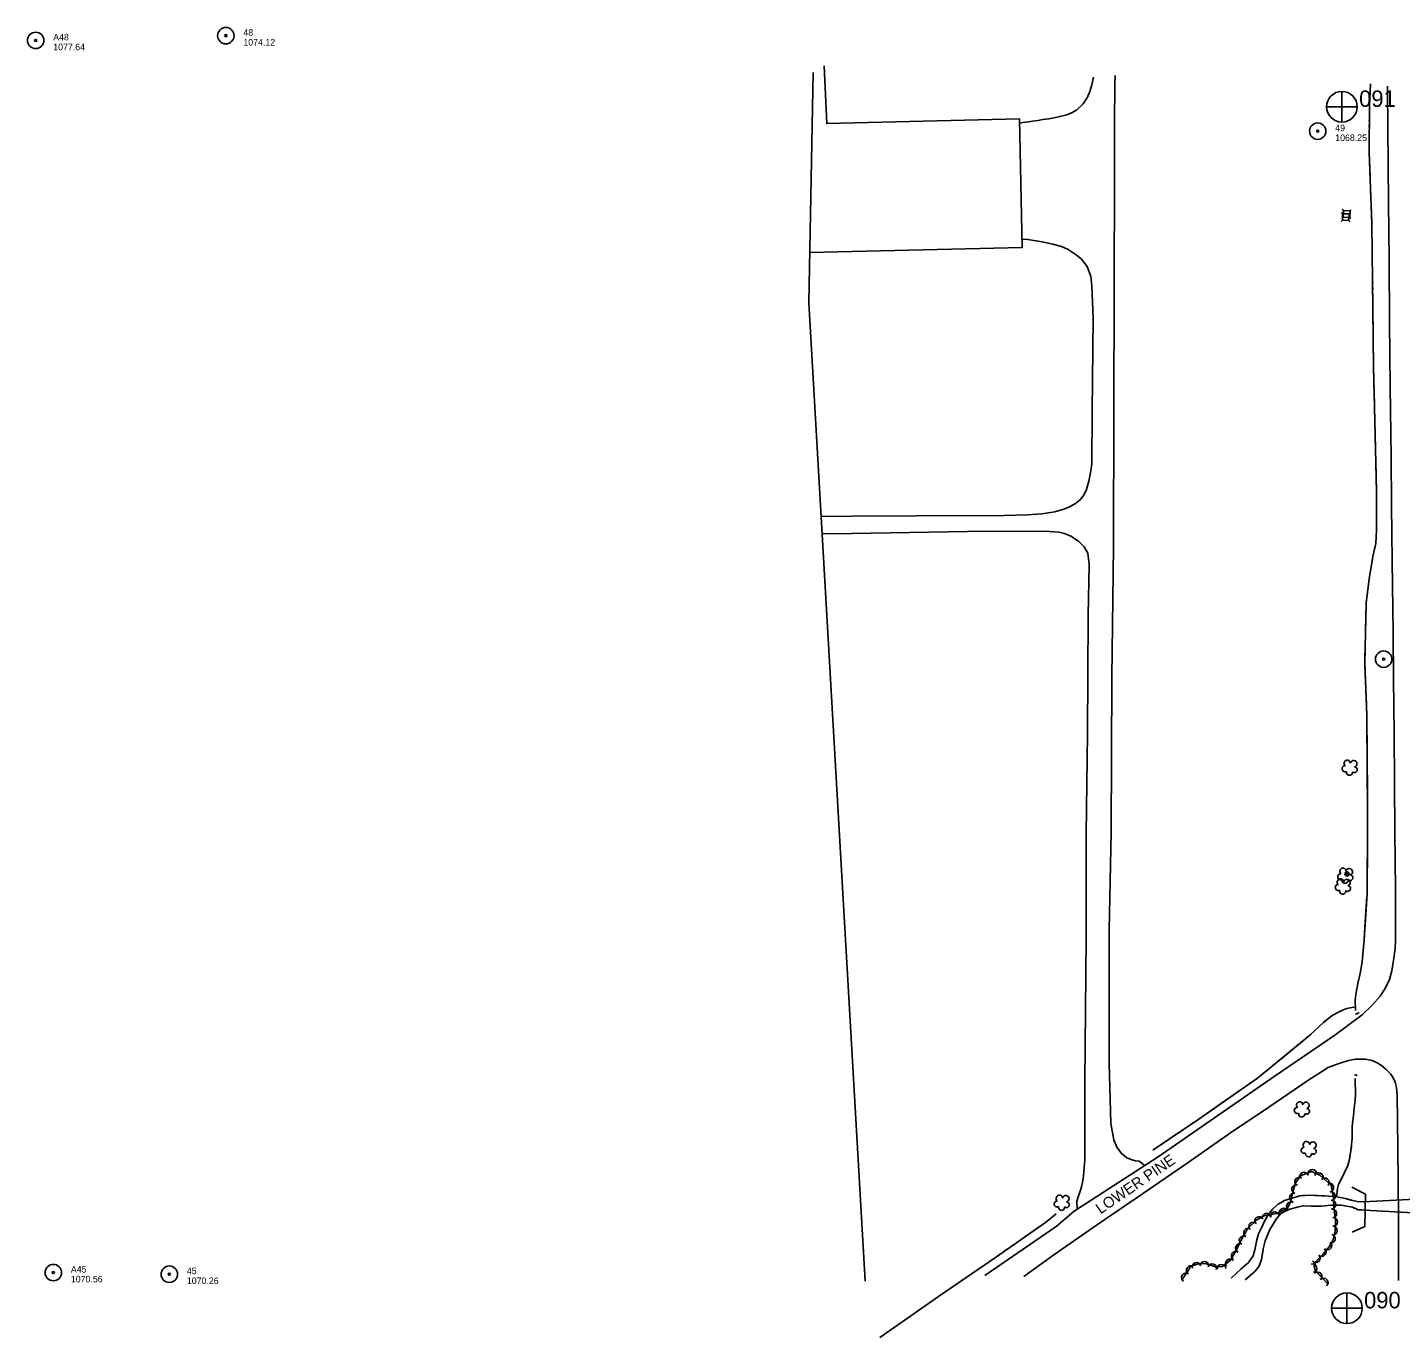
# Model space of a CAD drawing. Extents: x 296471 to 298842, y 32694 to 33905.
# Drawn here: x 296471 to 297724, y 32709 to 33905 of the extents above; entities that cross this region are included whole.
import ezdxf

# ---------------------------------------------------------------- set-up
doc = ezdxf.new("R2010")
doc.units = 0
for name, color, linetype in [('Level 11', 7, 'Continuous'), ('Level 12', 7, 'Continuous'), ('Level 14', 7, 'Continuous'), ('Level 15', 7, 'Continuous'), ('Level 17', 7, 'Continuous'), ('Level 18', 7, 'Continuous'), ('Level 19', 7, 'Continuous'), ('Level 21', 7, 'Continuous'), ('Level 4', 7, 'Continuous'), ('Level 6', 7, 'Continuous')]:
    doc.layers.add(name, color=color, linetype=linetype)

msp = doc.modelspace()

# ---------------------------------------------------------------- linework, layer by layer
at = {"layer": 'Level 11'}
for points in [[(297344.7, 32765.2), (297409.9, 32810.2), (297426.2, 32824), (297502.8, 32873.7), (297558.2, 32912.2), (297608.7, 32947), (297664.1, 32984.7), (297689.1, 33003.3), (297698.6, 33012.6), (297705.7, 33020.4), (297710.2, 33027.4), (297714.2, 33035.7), (297716.4, 33043.5), (297718.2, 33055.2), (297719.3, 33064.1), (297719.7, 33071.4), (297719.7, 33117.8), (297719, 33170.7), (297718.6, 33215.3), (297718.3, 33260.3), (297717.9, 33309.9), (297717.4, 33352.7), (297716.6, 33417.8), (297716, 33468.9), (297715.6, 33512.7), (297714.7, 33577.5), (297714, 33636.1), (297713.8, 33692.7), (297713.3, 33745.3), (297712.7, 33813.4), (297712.4, 33849.3), (297712.3, 33851.6)], [(297722.3, 32760.6), (297722.3, 32819.6), (297721.6, 32881.8), (297721, 32930.2), (297720.4, 32937), (297719.2, 32942), (297717.5, 32945.9), (297715.2, 32949.3), (297710.8, 32953.9), (297706.9, 32957.1), (297702.8, 32959.7), (297698.4, 32961.7), (297692.3, 32962.8), (297687, 32963), (297683, 32962.8), (297676.7, 32961.7), (297671.7, 32960.2), (297665.5, 32958.2), (297658.2, 32955.4), (297638.7, 32942.7), (297603.9, 32919), (297569, 32895.5), (297530.3, 32868.6), (297488.5, 32840), (297447.6, 32811.9), (297407.8, 32784.1), (297380.3, 32764.4)]]:
    msp.add_lwpolyline(points, dxfattribs=at)
at = {"layer": 'Level 12'}
msp.add_lwpolyline([(297198, 33870.4), (297200.4, 33817.6), (297376.3, 33821.9), (297378.8, 33704.4), (297184.8, 33699.8)], dxfattribs=at)
at = {"layer": 'Level 14'}
for radius in [2.02, 1.52, 1.01, 0.502]:
    msp.add_circle((297675.4, 33132.1), radius, dxfattribs=at)
at = {"layer": 'Level 15'}
msp.add_lwpolyline([(297680.1, 32805), (297691.7, 32810.2), (297692.1, 32839.5), (297679.8, 32846.1)], dxfattribs=at)
for centre, radius, start, end in [((297684, 33006.3), 2.06, 242.9145, 349.154), ((297683.2, 32947), 1.56, 26.0747, 132.3143)]:
    msp.add_arc(centre, radius, start, end, dxfattribs=at)
at = {"layer": 'Level 17'}
for points in [[(297490.6, 32865.8), (297485.6, 32869.7), (297482.1, 32870.2), (297479.1, 32870.9), (297474.4, 32872.9), (297469.3, 32876.7), (297465.2, 32882.5), (297462.4, 32889.3), (297459.6, 32904.3), (297458.1, 32959.2), (297458.2, 33081.2), (297459.9, 33170), (297460.5, 33311.8), (297462, 33430.7), (297462.5, 33555.4), (297462.7, 33664.9), (297463.1, 33773.8), (297463.2, 33831.3), (297463.4, 33840.4), (297463.5, 33848.7), (297463.5, 33854.7), (297463.7, 33860.4), (297463.7, 33861.6)], [(297444, 33859.8), (297442.4, 33852.8), (297440.5, 33846.7), (297438.3, 33841.6), (297434.6, 33835.7), (297428.5, 33829.7), (297423.9, 33827.2), (297419.4, 33825.6), (297413.1, 33823.9), (297408, 33822.9), (297403, 33821.9), (297397.7, 33821.2), (297393.3, 33820.4), (297388.3, 33819.6), (297382.6, 33818.8), (297379.5, 33818.5), (297376.6, 33818), (297376.4, 33818)], [(297378.6, 33711.9), (297384, 33711.6), (297396.9, 33709.6), (297406.8, 33707.4), (297414.6, 33705.1), (297420.9, 33702.4), (297428.2, 33697.7), (297433, 33693.8), (297438.2, 33686.9), (297441.3, 33677.8), (297442.5, 33669.2), (297443.5, 33639.9), (297442.8, 33554.8), (297442.5, 33506.6), (297441.5, 33500.3), (297439.6, 33490.8), (297437.6, 33483.2), (297435.3, 33478.6), (297432, 33474.3), (297427.6, 33470.4), (297422.1, 33467.5), (297416.7, 33465.2), (297408.5, 33463), (297396.6, 33461.1), (297383.5, 33460), (297362.3, 33459.6), (297281.9, 33459.1), (297223.8, 33458.9), (297195.2, 33458.6)], [(297196.1, 33442.8), (297222.8, 33443.1), (297328.8, 33445), (297392.7, 33445.1), (297404.1, 33444.9), (297412.4, 33444.2), (297417.4, 33443.1), (297423.3, 33440.8), (297430.3, 33436), (297435.4, 33430.8), (297438.6, 33425), (297440, 33414.9), (297439.1, 33368.6), (297438.3, 33260.1), (297437.3, 33168.7), (297437.3, 33073.1), (297436.1, 32942.3), (297436.1, 32870.3), (297435.4, 32864.4), (297434.7, 32856.3), (297433.9, 32850.4), (297432.9, 32846.4), (297431.3, 32841.4), (297430.2, 32838), (297428.8, 32833.3), (297428.9, 32825.8)]]:
    msp.add_lwpolyline(points, dxfattribs=at)
at = {"layer": 'Level 18'}
msp.add_lwpolyline([(297658.2, 32757.2), (297653.4, 32762.6), (297650.2, 32765.6), (297649.1, 32766.9), (297648.9, 32767.1), (297646.4, 32769.9), (297645.5, 32773.5), (297646.8, 32778.1), (297652.6, 32784), (297659.1, 32791.5), (297662.3, 32797.2), (297664.5, 32805.8), (297664.7, 32816.8), (297663.3, 32826.7), (297663.1, 32836.3), (297660.9, 32847.9), (297650.5, 32857), (297643, 32860.2), (297633.4, 32856.8), (297628.4, 32849.9), (297625.5, 32840.1), (297623.8, 32832.3), (297620.8, 32826.6), (297610.9, 32821.8), (297599.7, 32819.7), (297593.1, 32816.3), (297584.6, 32807.9), (297579, 32798.1), (297573.8, 32787.4), (297568.9, 32779.4), (297561.6, 32773.5), (297555.4, 32773.1), (297547.2, 32776), (297540.7, 32776.2), (297532.7, 32773.8), (297524.4, 32761.2)], dxfattribs=at)
for centre, radius, start, end in [((297675.6, 33233.1), 2.97, 6.381, 227.6149), ((297681.5, 33232.8), 2.97, 284.0318, 167.0051), ((297673.6, 33228.2), 2.78, 89.3519, 297.1249), ((297677.6, 33225), 2.78, 166.0289, 7.04), ((297682.1, 33227.3), 2.61, 228.7371, 86.6697), ((297671.7, 33134.5), 2.97, 6.381, 227.6149), ((297677.5, 33134.1), 2.97, 284.0318, 167.0051), ((297667.4, 33119.7), 2.78, 89.3519, 297.1249), ((297669.4, 33124.6), 2.97, 6.381, 227.6149), ((297669.6, 33129.5), 2.78, 89.3519, 297.1249), ((297673.6, 33126.3), 2.78, 166.0289, 7.04), ((297675.3, 33124.3), 2.97, 284.0318, 167.0051), ((297675.9, 33118.8), 2.61, 228.7371, 86.6697), ((297678.1, 33128.6), 2.61, 228.7371, 86.6697), ((297671.4, 33116.5), 2.78, 166.0289, 7.04), ((297632.1, 32921), 2.97, 6.381, 227.6149), ((297637.9, 32920.7), 2.97, 284.0318, 167.0051), ((297630, 32916), 2.78, 89.3519, 297.1249), ((297634, 32912.9), 2.78, 166.0289, 7.04), ((297638.5, 32915.2), 2.61, 228.7371, 86.6697), ((297638.3, 32884.7), 2.97, 6.381, 227.6149), ((297644.2, 32884.3), 2.97, 284.0318, 167.0051), ((297636.3, 32879.7), 2.78, 89.3519, 297.1249), ((297640.2, 32876.5), 2.78, 166.0289, 7.04), ((297644.7, 32878.8), 2.61, 228.7371, 86.6697), ((297636.1, 32855.6), 4, 19.3934, 199.3781), ((297643.7, 32858.2), 4, 19.3934, 199.3781), ((297649.5, 32855.2), 4, 337.1115, 157.0962), ((297628.9, 32844.2), 4, 73.4794, 253.4641), ((297631.7, 32850.9), 4, 54.5968, 234.5815), ((297655, 32850.3), 4, 318.7866, 138.7713), ((297659.2, 32845.6), 4, 280.671, 100.6557), ((297410.8, 32830.7), 2.78, 89.3519, 297.1249), ((297412.8, 32835.7), 2.97, 6.381, 227.6149), ((297418.6, 32835.4), 2.97, 284.0318, 167.0051), ((297626.9, 32836.6), 4, 77.1608, 257.1455), ((297660.7, 32837.7), 4, 280.671, 100.6557), ((297661.1, 32830.1), 4, 271.1842, 91.1689), ((297414.7, 32827.6), 2.78, 166.0289, 7.04), ((297419.2, 32829.9), 2.61, 228.7371, 86.6697), ((297601.8, 32817.9), 4, 10.7746, 190.7592), ((297609.6, 32819.4), 4, 10.7746, 190.7592), ((297617.5, 32822.7), 4, 25.9964, 205.9811), ((297624.2, 32828.6), 4, 62.0828, 242.0675), ((297661.9, 32821.9), 4, 278.0185, 98.0032), ((297585, 32804.4), 4, 60.3697, 240.3543), ((297589.7, 32810), 4, 44.4675, 224.4521), ((297595.1, 32815), 4, 27.3513, 207.336), ((297662.4, 32806.3), 4, 268.6723, 88.657), ((297662.6, 32814.3), 4, 268.6723, 88.657), ((297581, 32797.4), 4, 60.3697, 240.3543), ((297657.5, 32792.8), 4, 229.1513, 49.136), ((297660.6, 32799), 4, 256.1978, 76.1824), ((297573.7, 32783.2), 4, 58.5145, 238.4992), ((297577.6, 32790.4), 4, 64.0908, 244.0754), ((297646.8, 32781.1), 4, 225.0913, 45.076), ((297652.2, 32786.7), 4, 229.1513, 49.136), ((297532.7, 32770.1), 4, 56.5107, 236.4954), ((297538, 32773.2), 4, 16.608, 196.5927), ((297545.2, 32774), 4, 358.6263, 178.611), ((297552.2, 32772), 4, 340.1817, 160.1664), ((297560.8, 32771.4), 4, 4.2403, 184.225), ((297568.4, 32776.3), 4, 38.9198, 218.9045), ((297643.7, 32771.9), 4, 284.1974, 104.1821), ((297528.3, 32763.4), 4, 56.5107, 236.4954), ((297648.4, 32764.5), 4, 311.0368, 131.0215), ((297654, 32758.8), 4, 312.0721, 132.0568)]:
    msp.add_arc(centre, radius, start, end, dxfattribs=at)
at = {"layer": 'Level 19'}
for points in [[(297683.2, 33007.4), (297682.9, 33017.2), (297683.6, 33023.9), (297685.2, 33032), (297687.4, 33041.1), (297689.1, 33051.7), (297690.9, 33071.8), (297693.7, 33114), (297694, 33161.2), (297693.9, 33204.5), (297693.3, 33277.2), (297691.7, 33325), (297692.7, 33379.6), (297695.9, 33403.7), (297698.9, 33422), (297701.6, 33434), (297702.2, 33445.8), (297702.4, 33481.2), (297701.1, 33533.5), (297699.5, 33594.6), (297698.7, 33673.9), (297698.1, 33726.1), (297695.5, 33791.3), (297695.9, 33833.4), (297696.7, 33853.8)], [(297695.8, 33825.9), (297695.9, 33833.4), (297696.7, 33853.8)], [(297695.7, 33820.1), (297695.8, 33822.1)], [(297695.7, 33814.3), (297695.7, 33816.3)], [(297696.1, 33776.8), (297695.5, 33791.3), (297695.6, 33804.7)], [(297695.6, 33808.6), (297695.7, 33810.5)], [(297697.2, 33748.8), (297696.1, 33776.8)], [(297697.4, 33743), (297697.4, 33745)], [(297697.7, 33737.3), (297697.6, 33739.2)], [(297697.9, 33731.5), (297697.8, 33733.4)], [(297698.4, 33699.7), (297698.1, 33726.1), (297698.1, 33727.6)], [(297698.8, 33671.7), (297698.7, 33673.9), (297698.4, 33699.7)], [(297698.8, 33665.9), (297698.8, 33667.9)], [(297698.9, 33660.2), (297698.9, 33662.1)], [(297698.9, 33654.4), (297698.9, 33656.3)], [(297699.3, 33622.6), (297699, 33650.5)], [(297699.5, 33594.6), (297699.3, 33622.6)], [(297699.7, 33588.8), (297699.6, 33590.8)], [(297699.8, 33583.1), (297699.8, 33585)], [(297700, 33577.3), (297699.9, 33579.2)], [(297700.8, 33545.5), (297700.1, 33573.4)], [(297701.5, 33517.5), (297701.1, 33533.5), (297700.8, 33545.5)], [(297701.6, 33511.7), (297701.6, 33513.7)], [(297701.8, 33506), (297701.7, 33507.9)], [(297701.9, 33500.2), (297701.9, 33502.1)], [(297702.3, 33468.4), (297702.4, 33481.2), (297702, 33496.3)], [(297701.9, 33440.4), (297702.2, 33445.8), (297702.3, 33468.4)], [(297701.7, 33434.7), (297701.7, 33436.6)], [(297699.2, 33423.4), (297699.6, 33425.2)], [(297700.5, 33429), (297700.9, 33430.9)], [(297694.3, 33391.9), (297695.9, 33403.7), (297698.5, 33419.6)], [(297692.4, 33364.1), (297692.7, 33379.6), (297694.3, 33391.9)], [(297692.3, 33358.3), (297692.3, 33360.2)], [(297692.1, 33346.7), (297692.1, 33348.7)], [(297692.2, 33352.5), (297692.2, 33354.4)], [(297692, 33314.9), (297691.7, 33325), (297692, 33342.9)], [(297693, 33287), (297692, 33314.9)], [(297693.2, 33281.2), (297693.1, 33283.1)], [(297693.3, 33275.4), (297693.3, 33277.2), (297693.3, 33277.4)], [(297693.4, 33269.7), (297693.3, 33271.6)], [(297693.6, 33237.8), (297693.4, 33265.8)], [(297693.8, 33209.9), (297693.6, 33237.8)], [(297693.9, 33204.1), (297693.9, 33204.5), (297693.8, 33206)], [(297693.9, 33198.3), (297693.9, 33200.3)], [(297693.9, 33192.5), (297693.9, 33194.5)], [(297694, 33160.7), (297694, 33161.2), (297693.9, 33188.7)], [(297693.8, 33132.8), (297694, 33160.7)], [(297693.7, 33121.2), (297693.7, 33123.1)], [(297693.8, 33127), (297693.8, 33128.9)], [(297691.7, 33083.7), (297693.5, 33111.6)], [(297693.7, 33115.4), (297693.7, 33117.4)], [(297689.5, 33055.8), (297690.9, 33071.8), (297691.7, 33083.7)], [(297687.9, 33044.4), (297688.2, 33046.3)], [(297688.8, 33050.1), (297689.1, 33051.7), (297689.1, 33052)], [(297683.2, 33007.4), (297682.9, 33017.2), (297683.6, 33023.9), (297685.2, 33032), (297685.9, 33035)], [(297686.8, 33038.7), (297687.2, 33040.6)], [(297498, 32879.8), (297539, 32907.6), (297593.7, 32945.7), (297641.4, 32984.7), (297653.8, 32996.5), (297661.8, 33002.9), (297668.1, 33006.3), (297672.8, 33008.4), (297675.3, 33009.2), (297676.6, 33009.5), (297683.1, 33010.8)], [(297658.3, 33000.1), (297661.8, 33002.9), (297668.1, 33006.3), (297672.8, 33008.4), (297675.3, 33009.2), (297676.6, 33009.5), (297683.1, 33010.8)], [(297653.9, 32996.6), (297655.4, 32997.7)], [(297621.6, 32968.5), (297641.4, 32984.7), (297642.9, 32986.1)], [(297645.6, 32988.7), (297647, 32990)], [(297649.7, 32992.6), (297651.1, 32993.9)], [(297600.2, 32951), (297621.6, 32968.5)], [(297595.8, 32947.4), (297597.3, 32948.6)], [(297560.8, 32922.8), (297583.5, 32938.6)], [(297586.6, 32940.7), (297588.1, 32941.8)], [(297591.3, 32944), (297592.8, 32945.1)], [(297665.7, 32837.3), (297666.8, 32844.8), (297667.7, 32848.5), (297670.2, 32853.6), (297673.2, 32859.5), (297676, 32865.9), (297677.6, 32871.6), (297678.9, 32879.4), (297679.5, 32884.9), (297679.9, 32890.5), (297680.1, 32896.6), (297680.2, 32901.5), (297680.6, 32906.7), (297681.2, 32911.4), (297682, 32918.3), (297682.7, 32925.5), (297683, 32930.7), (297683.1, 32935.7), (297682.9, 32939.6), (297682.9, 32945.2)], [(297680.5, 32905.2), (297680.6, 32906.7), (297681.2, 32911.4), (297682, 32918.3), (297682.7, 32925.5), (297683, 32930.7), (297683.1, 32935.7), (297682.9, 32939.6), (297682.9, 32945.2)], [(297538.2, 32907), (297539, 32907.6), (297560.8, 32922.8)], [(297524, 32897.4), (297525.6, 32898.5)], [(297528.7, 32900.6), (297530.3, 32901.7)], [(297533.5, 32903.8), (297535, 32904.9)], [(297680.1, 32896.9), (297680.1, 32899.7)], [(297498, 32879.8), (297520.9, 32895.3)], [(297679, 32880.4), (297679.3, 32883.2)], [(297679.7, 32888.6), (297679.9, 32890.5), (297679.9, 32891.4)], [(297665.7, 32837.3), (297666.8, 32844.8), (297667.7, 32848.5), (297670.2, 32853.6), (297673.2, 32859.5), (297676, 32865.9), (297677.6, 32871.6), (297678.2, 32874.9)], [(297569.6, 32763), (297578.5, 32771), (297585.3, 32777.2), (297589.7, 32783.4), (297591.2, 32788.9), (297592.9, 32797.9), (297594.6, 32803.5), (297597.5, 32809.4), (297600.1, 32814.9), (297603.1, 32820.1), (297607.3, 32826), (297612.4, 32830.5), (297618.3, 32833.9), (297625.2, 32836.1), (297632.3, 32838.1), (297640.7, 32838.6), (297655, 32838.1), (297666.2, 32837.2), (297673.9, 32835.7), (297679.5, 32834), (297684.7, 32832.8), (297690.4, 32832.5), (297790.9, 32837.7)], [(297607.3, 32826), (297607.3, 32826), (297612.4, 32830.5), (297618.3, 32833.9), (297625.2, 32836.1), (297631.4, 32837.8)], [(297635.1, 32838.3), (297637, 32838.4)], [(297640.8, 32838.6), (297642.6, 32838.5)], [(297646.4, 32838.4), (297648.3, 32838.3)], [(297652, 32838.2), (297655, 32838.1), (297666.2, 32837.2), (297673.9, 32835.7), (297678.9, 32834.1)], [(297678.9, 32834.1), (297679.5, 32834), (297684.7, 32832.8), (297690.4, 32832.5), (297692, 32832.6)], [(297248.9, 32708.6), (297302.4, 32746.2), (297355.2, 32782.4), (297400.2, 32813.8), (297409.9, 32821.7)], [(297381.2, 32800.6), (297400.2, 32813.8), (297409.9, 32821.7)], [(297582.5, 32761.3), (297591.6, 32769.3), (297595, 32773.7), (297597.2, 32779.8), (297598.9, 32789.8), (297600.5, 32796.9), (297605, 32807.4), (297610.8, 32816.9), (297615, 32821.8), (297622.3, 32825.7), (297631.2, 32828.1), (297635.5, 32828.8), (297642.7, 32828.7), (297651.7, 32828.5), (297660.5, 32829.7), (297669.9, 32829.7), (297680.3, 32827.6), (297683.6, 32826.3), (297685.5, 32825.4), (297780.4, 32820.2)], [(297594.2, 32802.1), (297594.6, 32803.5), (297597.5, 32809.4), (297600.1, 32814.9), (297603.1, 32820.1), (297607.3, 32826)], [(297608, 32812.3), (297610.8, 32816.9), (297615, 32821.8), (297622.3, 32825.7), (297631.2, 32828.1), (297635.2, 32828.8)], [(297635.2, 32828.8), (297635.5, 32828.8), (297642.7, 32828.7), (297651.7, 32828.5), (297660.5, 32829.7), (297668.5, 32829.7)], [(297673.1, 32829.1), (297675.3, 32828.6)], [(297679.8, 32827.7), (297680.3, 32827.6), (297682, 32826.9)], [(297686.3, 32825.4), (297688.6, 32825.3)], [(297604.5, 32806.3), (297605, 32807.4), (297605.6, 32808.3)], [(297375.1, 32796.3), (297377.1, 32797.7)], [(297592.7, 32796.7), (297592.9, 32797.9), (297593.1, 32798.5)], [(297599.7, 32793.4), (297600.2, 32795.7)], [(297601.8, 32800), (297602.7, 32802.1)], [(297329.6, 32764.8), (297355.2, 32782.4), (297359, 32785.1)], [(297363, 32787.9), (297365.1, 32789.3)], [(297369.1, 32792.1), (297371.1, 32793.5)], [(297582.5, 32761.3), (297591.6, 32769.3), (297595, 32773.7), (297597.2, 32779.8), (297598.8, 32788.9)], [(297590.3, 32785.6), (297590.8, 32787.4)], [(297591.7, 32791.1), (297592, 32793)], [(297569.6, 32763), (297578.5, 32771), (297585.3, 32777.2), (297588.8, 32782.2)], [(297300.2, 32744.7), (297302.4, 32746.2), (297329.6, 32764.8)], [(297282.1, 32731.9), (297284.1, 32733.4)], [(297288.2, 32736.2), (297290.2, 32737.6)], [(297294.2, 32740.4), (297296.2, 32741.8)], [(297248.9, 32708.6), (297278.1, 32729.1)]]:
    msp.add_lwpolyline(points, dxfattribs=at)
at = {"layer": 'Level 21'}
for p, q in [((297671.3, 33735.2), (297670.3, 33736.3)), ((297672.1, 33738), (297671, 33739.1)), ((297678.4, 33736), (297677.3, 33735)), ((297679.2, 33738.8), (297678.1, 33737.8)), ((297671.1, 33729.2), (297670, 33728.2)), ((297671.8, 33732), (297670.7, 33731)), ((297678.1, 33727.9), (297677.1, 33729)), ((297678.9, 33730.7), (297677.8, 33731.8))]:
    msp.add_line(p, q, dxfattribs=at)
for points in [[(297677.8, 33731.8), (297678.1, 33737.8), (297672.1, 33738), (297671.8, 33732)], [(297677.1, 33729), (297677.3, 33735), (297671.3, 33735.2), (297671.1, 33729.2)]]:
    msp.add_lwpolyline(points, close=True, dxfattribs=at)
at = {"layer": 'Level 4'}
for p, q in [((297670.7, 33846.9), (297670.6, 33819.1)), ((297656.8, 33832.9), (297684.7, 33832.9)), ((297675.2, 32749.4), (297675.2, 32721.6)), ((297661.3, 32735.4), (297689.2, 32735.4))]:
    msp.add_line(p, q, dxfattribs=at)
msp.add_lwpolyline([(297235.4, 32760), (297184, 33653.8), (297187.8, 33864.3)], dxfattribs=at)
for centre in [(297670.7, 33832.9), (297675.3, 32735.4)]:
    msp.add_circle(centre, 14, dxfattribs=at)
at = {"layer": 'Level 6'}
for centre, radius in [((296478.1, 33893.5), 7.5), ((296651.7, 33897.8), 7.5), ((296651.7, 33897.8), 0.96), ((296478.1, 33893.5), 0.96), ((297648.6, 33810.6), 7.5), ((297648.6, 33810.6), 0.96), ((297708.8, 33328.3), 7.5), ((297708.8, 33328.3), 0.96), ((296494.2, 32768), 7.5), ((296600.1, 32766.5), 7.5), ((296494.2, 32768), 0.96), ((296600.1, 32766.5), 0.96)]:
    msp.add_circle(centre, radius, dxfattribs=at)

# ---------------------------------------------------------------- texts
at = {"layer": 'Level 11'}
msp.add_text('LOWER PINE', height=10, rotation=34.4233, dxfattribs=at).set_placement((297450.3, 32821))
at = {"layer": 'Level 4'}
for s, p in [('091', (297686.4, 33832.8)), ('090', (297690.9, 32735.3))]:
    msp.add_text(s, height=15, dxfattribs=at).set_placement(p)
at = {"layer": 'Level 6'}
for s, p in [('A48', (296494.1, 33893.5)), ('48', (296667.7, 33897.8)), ('1077.64', (296494.1, 33884.5)), ('1074.12', (296667.7, 33888.8)), ('49', (297664.6, 33810.6)), ('1068.25', (297664.6, 33801.6)), ('A45', (296510.2, 32768)), ('45', (296616.1, 32766.5)), ('1070.56', (296510.2, 32759)), ('1070.26', (296616.1, 32757.5))]:
    msp.add_text(s, height=6, dxfattribs=at).set_placement(p)

doc.saveas('drawing.dxf')
